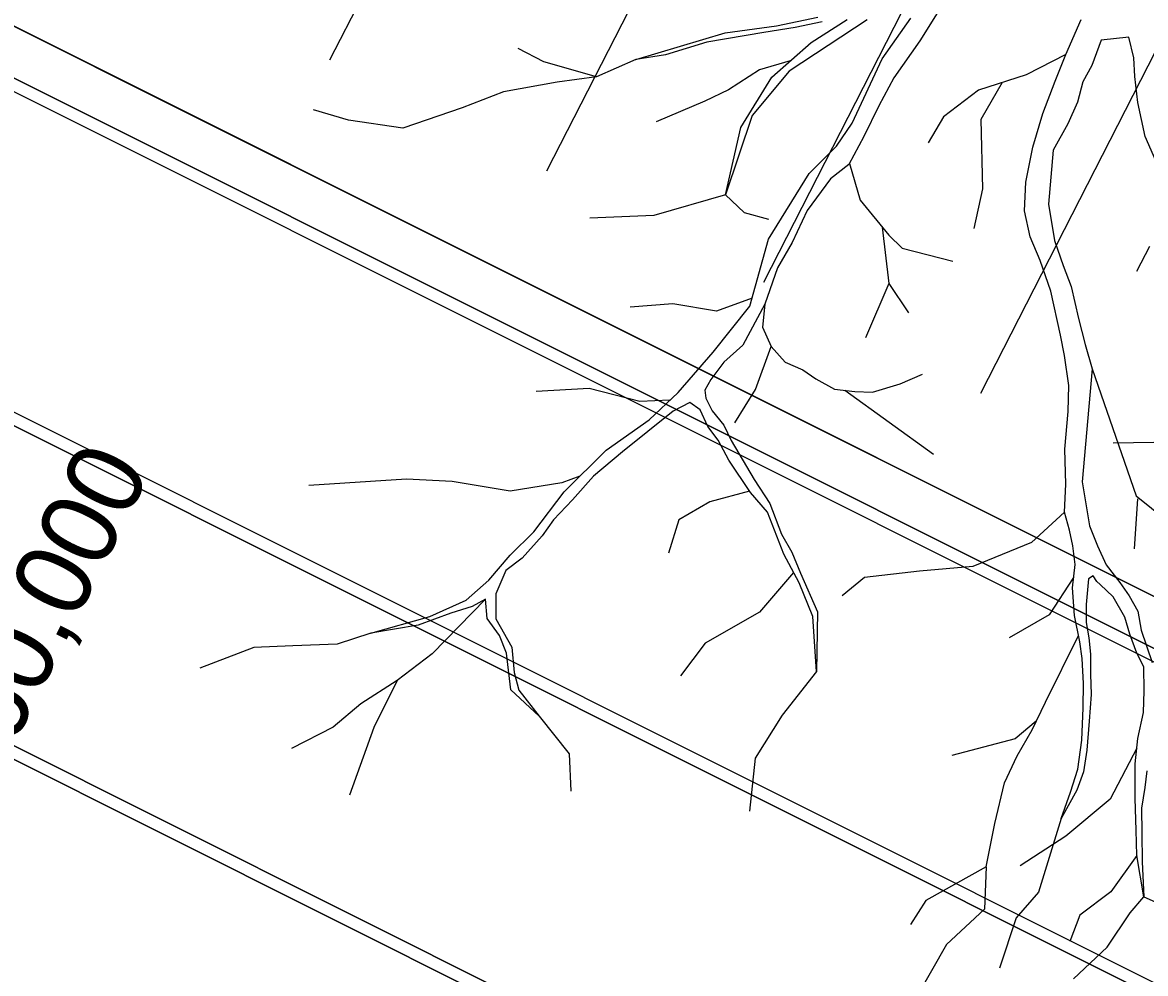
# Model space of a CAD drawing. Extents: x -504998 to -504814, y -1117353 to -1117234.
# Drawn here: x -504939.208 to -504934.599, y -1117264.364 to -1117260.463 of the extents above; entities that cross this region are included whole.
import ezdxf

# ---------------------------------------------------------------- set-up
doc = ezdxf.new("R2010")
doc.units = 0
for name, color, linetype in [('01_ST tenká', 7, 'Continuous'), ('03_POPIS', 7, 'Continuous'), ('10_STROMY', 7, 'Continuous'), ('_01_pl', 7, 'Continuous'), ('_01_sport_plochy', 7, 'Continuous'), ('_01_ST tenká', 7, 'Continuous'), ('_01_svah', 7, 'Continuous'), ('Default', 7, 'Continuous')]:
    doc.layers.add(name, color=color, linetype=linetype)

# ---------------------------------------------------------------- blocks, each defined once
blk = doc.blocks.new('stromm')
at = {"layer": 'Default'}
for p, q in [((-0.00824, -0.06434), (-0.02324, -0.07284)), ((-0.21026, -0.07639), (-0.22054, -0.07159)), ((-0.17472, -0.07388), (-0.1897, -0.08118)), ((-0.1149, -0.07164), (-0.12664, -0.0757)), ((-0.02324, -0.07284), (-0.04142, -0.0797)), ((-0.1897, -0.08118), (-0.21026, -0.07639)), ((-0.12664, -0.0757), (-0.13829, -0.08392)), ((-0.03233, -0.07627), (-0.03997, -0.09098)), ((-0.1897, -0.08118), (-0.20478, -0.08392)), ((-0.04142, -0.0797), (-0.05445, -0.09066)), ((-0.20478, -0.08392), (-0.22534, -0.08872)), ((-0.13829, -0.08392), (-0.1472, -0.08872)), ((-0.22534, -0.08872), (-0.24111, -0.09557)), ((-0.1472, -0.08872), (-0.16571, -0.09763)), ((-0.05445, -0.09066), (-0.05993, -0.10094)), ((-0.03997, -0.09098), (-0.03808, -0.11784)), ((-0.24111, -0.09557), (-0.26372, -0.10448)), ((-0.28497, -0.10242), (-0.29868, -0.099)), ((-0.26372, -0.10448), (-0.28497, -0.10242)), ((-0.09014, -0.11038), (-0.08529, -0.12438)), ((-0.03808, -0.11784), (-0.04073, -0.13334)), ((-0.13757, -0.12471), (-0.16502, -0.13395)), ((-0.13757, -0.12471), (-0.13006, -0.13121)), ((-0.08529, -0.12438), (-0.07364, -0.1374)), ((-0.16502, -0.13395), (-0.1897, -0.13601)), ((-0.13006, -0.13121), (-0.12047, -0.13326)), ((-0.07631, -0.13441), (-0.07272, -0.15613)), ((-0.07364, -0.1374), (-0.06815, -0.1422)), ((0.02756, -0.13717), (0.02303, -0.14714)), ((-0.06815, -0.1422), (-0.04838, -0.1464)), ((-0.07272, -0.15613), (-0.08084, -0.17762)), ((-0.07272, -0.15613), (-0.06461, -0.16708)), ((-0.12546, -0.16419), (-0.13899, -0.16982)), ((-0.15613, -0.16777), (-0.17257, -0.16982)), ((-0.13899, -0.16982), (-0.15613, -0.16777)), ((-0.12045, -0.16626), (-0.12098, -0.17524)), ((-0.12098, -0.17524), (-0.11728, -0.18264)), ((-0.12257, -0.19955), (-0.11728, -0.18264)), ((-0.11728, -0.18264), (-0.11147, -0.18845)), ((0.0075, -0.18561), (0.02679, -0.23402)), ((-0.11147, -0.18845), (-0.10459, -0.1911)), ((-0.10459, -0.1911), (-0.09931, -0.19427)), ((-0.06654, -0.1948), (-0.05808, -0.19057)), ((-0.09931, -0.19427), (-0.09191, -0.19797)), ((-0.07711, -0.19849), (-0.06654, -0.1948)), ((-0.12997, -0.21276), (-0.12257, -0.19955)), ((-0.09191, -0.19797), (-0.08398, -0.19849)), ((-0.08794, -0.19823), (-0.05241, -0.22145)), ((-0.08398, -0.19849), (-0.07711, -0.19849)), ((-0.18697, -0.20203), (-0.20753, -0.20409)), ((-0.16709, -0.20614), (-0.18697, -0.20203)), ((-0.15552, -0.20514), (-0.16709, -0.20614)), ((0.01698, -0.21385), (0.03274, -0.21288)), ((0.02679, -0.23402), (0.03913, -0.24293)), ((0.02733, -0.23514), (0.02698, -0.25449)), ((-0.19588, -0.23904), (-0.21576, -0.24315)), ((-0.18908, -0.2362), (-0.19588, -0.23904)), ((-0.12308, -0.23896), (-0.13831, -0.24383)), ((-0.2562, -0.24041), (-0.2939, -0.24452)), ((-0.23838, -0.24041), (-0.2562, -0.24041)), ((-0.21576, -0.24315), (-0.23838, -0.24041)), ((-0.13831, -0.24383), (-0.14996, -0.25137)), ((-0.00068, -0.24161), (-0.01296, -0.25389)), ((-0.14996, -0.25137), (-0.15339, -0.26439)), ((-0.01296, -0.25389), (-0.03525, -0.26417)), ((-0.03525, -0.26417), (-0.05582, -0.26692)), ((-0.10458, -0.26969), (-0.11706, -0.28564)), ((-0.05582, -0.26692), (-0.07706, -0.27034)), ((0.004, -0.2667), (-0.0048, -0.2816)), ((-0.07706, -0.27034), (-0.08529, -0.27788)), ((-0.0048, -0.2816), (-0.01988, -0.29119)), ((-0.22348, -0.28543), (-0.24318, -0.30756)), ((-0.11706, -0.28564), (-0.13762, -0.29865)), ((-0.00472, -0.31547), (0.0069, -0.2891)), ((-0.13762, -0.29865), (-0.14653, -0.31167)), ((-0.26725, -0.30058), (-0.28019, -0.30551)), ((-0.31241, -0.30825), (-0.33297, -0.31716)), ((-0.29733, -0.30688), (-0.31241, -0.30825)), ((-0.28019, -0.30551), (-0.29733, -0.30688)), ((-0.24318, -0.30756), (-0.2562, -0.31852)), ((-0.09402, -0.30757), (-0.10654, -0.32516)), ((-0.00942, -0.32642), (-0.00472, -0.31547)), ((-0.2562, -0.31852), (-0.26991, -0.32812)), ((-0.2562, -0.31852), (-0.26442, -0.33703)), ((-0.10654, -0.32516), (-0.11613, -0.3423)), ((-0.00793, -0.32294), (-0.01577, -0.33025)), ((-0.01474, -0.33675), (-0.00942, -0.32642)), ((-0.26991, -0.32812), (-0.28019, -0.33771)), ((-0.20059, -0.32986), (-0.18834, -0.34388)), ((-0.01577, -0.33025), (-0.04011, -0.33779)), ((0.03149, -0.33171), (0.02199, -0.35189)), ((-0.28019, -0.33771), (-0.29596, -0.34662)), ((-0.26442, -0.33703), (-0.27265, -0.36376)), ((-0.01913, -0.34738), (-0.01474, -0.33675)), ((-0.18834, -0.34388), (-0.18697, -0.35827)), ((-0.11613, -0.3423), (-0.1175, -0.36285)), ((-0.02226, -0.36334), (-0.01913, -0.34738)), ((0.02199, -0.35189), (0.00554, -0.36696)), ((0.00343, -0.36018), (-0.00412, -0.38918)), ((-0.02476, -0.38024), (-0.02226, -0.36334)), ((0.00554, -0.36696), (-0.01159, -0.3793)), ((0.03338, -0.37322), (0.02399, -0.38781)), ((-0.02476, -0.38024), (-0.04759, -0.39437)), ((-0.02476, -0.38024), (-0.02468, -0.39672)), ((-0.00412, -0.38918), (-0.01234, -0.39946)), ((0.02399, -0.38781), (0.01233, -0.39741)), ((0.03174, -0.39551), (0.03679, -0.38911)), ((0.03679, -0.38911), (0.04716, -0.39322)), ((-0.04759, -0.39437), (-0.05307, -0.40397)), ((0.02355, -0.40928), (0.03174, -0.39551)), ((-0.02468, -0.39672), (-0.03874, -0.41111)), ((-0.01234, -0.39946), (-0.01782, -0.41934)), ((0.01233, -0.39741), (0.00891, -0.40769)), ((0.02355, -0.40928), (0.01096, -0.42208)), ((-0.03874, -0.41111), (-0.04902, -0.43099))]:
    blk.add_line(p, q, dxfattribs=at)
for points in [[(-0.05311, -0.04048), (-0.06495, -0.06163), (-0.07447, -0.07643), (-0.07975, -0.08753), (-0.08504, -0.09968), (-0.09032, -0.11078), (-0.09719, -0.11659), (-0.10565, -0.12927), (-0.11094, -0.14195), (-0.11622, -0.15199), (-0.12045, -0.16626), (-0.12825, -0.18252), (-0.13525, -0.18951), (-0.14001, -0.19638), (-0.14212, -0.20061), (-0.14159, -0.20378), (-0.13895, -0.20853), (-0.13419, -0.21382), (-0.13102, -0.21963), (-0.12151, -0.23443), (-0.11495, -0.24344), (-0.10988, -0.25504), (-0.10565, -0.26191), (-0.10195, -0.26983), (-0.09461, -0.28451), (-0.09402, -0.30757), (-0.09641, -0.28636), (-0.10223, -0.27365), (-0.10866, -0.26277), (-0.11575, -0.24681), (-0.1227, -0.23947), (-0.13164, -0.22739), (-0.13615, -0.21976), (-0.14033, -0.21468), (-0.14362, -0.2084), (-0.1478, -0.20572), (-0.15407, -0.2093), (-0.17294, -0.22598), (-0.18375, -0.23596), (-0.1915, -0.24538), (-0.19857, -0.25346), (-0.20261, -0.25986), (-0.21001, -0.26895), (-0.21608, -0.27399), (-0.21952, -0.2832), (-0.21909, -0.29287), (-0.21237, -0.30361), (-0.21103, -0.31337), (-0.20901, -0.3201), (-0.20059, -0.32986), (-0.21203, -0.3201), (-0.21439, -0.30596), (-0.21742, -0.29924), (-0.22247, -0.29284), (-0.22348, -0.28543), (-0.22853, -0.28846), (-0.23661, -0.29149), (-0.24906, -0.29668), (-0.26725, -0.30058), (-0.24469, -0.29318), (-0.23088, -0.28611), (-0.22247, -0.27803), (-0.21473, -0.26793), (-0.20597, -0.25851), (-0.19486, -0.24246), (-0.17935, -0.22566), (-0.16322, -0.21307), (-0.15245, -0.20197), (-0.13957, -0.18574), (-0.12618, -0.16732), (-0.12019, -0.14112), (-0.10559, -0.11494), (-0.09548, -0.10384), (-0.08972, -0.0947), (-0.07929, -0.06918), (-0.06889, -0.05302)], [(-0.08573, -0.05433), (-0.11504, -0.07565), (-0.12862, -0.09341), (-0.13757, -0.12471), (-0.13288, -0.09828), (-0.12174, -0.07826), (-0.10713, -0.06412), (-0.09358, -0.05464)], [(-0.10319, -0.05592), (-0.11355, -0.05868), (-0.12565, -0.0611), (-0.14751, -0.06582), (-0.16332, -0.07146), (-0.17472, -0.07388), (-0.1406, -0.06197), (-0.12081, -0.05834), (-0.10491, -0.05419)], [(0.02849, -0.10392), (0.02402, -0.09464), (0.02058, -0.08159), (0.01884, -0.07158), (0.01815, -0.06437), (0.01595, -0.05645), (0.00519, -0.05816), (0.00201, -0.06815), (-0.00109, -0.07467), (-0.0028, -0.08257), (-0.00624, -0.09116), (-0.01148, -0.10164), (-0.01232, -0.12256), (-0.00933, -0.1365), (-0.00555, -0.14611), (-0.00212, -0.15401), (0.00132, -0.16637), (0.00441, -0.17634), (0.0075, -0.18561), (0.00564, -0.2295), (0.00922, -0.2464), (0.01265, -0.25396), (0.01643, -0.26117), (0.02193, -0.26785), (0.02586, -0.27277), (0.02947, -0.27867), (0.03111, -0.28588), (0.0359, -0.2982)], [(0.0357, -0.3403), (0.03531, -0.34683), (0.03433, -0.35482), (0.03494, -0.36452), (0.03556, -0.37557), (0.03679, -0.38911), (0.03338, -0.37322), (0.03273, -0.36338), (0.03174, -0.35125), (0.03109, -0.33781), (0.03174, -0.32798), (0.03338, -0.31781), (0.03338, -0.30929), (0.03273, -0.30011), (0.02978, -0.29487), (0.02683, -0.28765), (0.02453, -0.2811), (0.01961, -0.27356), (0.01436, -0.26897), (0.01311, -0.2679), (0.01155, -0.26571), (0.00981, -0.26695), (0.00936, -0.27697), (0.00967, -0.28386), (0.01092, -0.28981), (0.01186, -0.29607), (0.01218, -0.30389), (0.0128, -0.31171), (0.01249, -0.32204), (0.01218, -0.3333), (0.01124, -0.34175), (0.00904, -0.34895), (0.00343, -0.36018), (0.00654, -0.34989), (0.00904, -0.34081), (0.00998, -0.32955), (0.00998, -0.31703), (0.00967, -0.30764), (0.00873, -0.29794), (0.00752, -0.29157), (0.00498, -0.28136), (0.00372, -0.27072), (0.00435, -0.26164), (0.0031, -0.25444), (0.00153, -0.2485), (-0.00068, -0.24161), (-0.00066, -0.23066), (-0.0016, -0.21721), (-0.00097, -0.2025), (-0.00128, -0.19248), (-0.00347, -0.18091), (-0.00535, -0.17308), (-0.0098, -0.15622), (-0.01456, -0.1446), (-0.01879, -0.13561), (-0.02143, -0.12557), (-0.02143, -0.11448), (-0.01931, -0.10074), (-0.01614, -0.08753), (-0.01191, -0.07484), (-0.00822, -0.06427), (-0.00293, -0.05053)], [(-0.05311, -0.04048), (-0.06495, -0.06163), (-0.07447, -0.07643), (-0.07975, -0.08753), (-0.08504, -0.09968), (-0.09032, -0.11078), (-0.09719, -0.11659), (-0.10565, -0.12927), (-0.11094, -0.14195), (-0.11622, -0.15199), (-0.12045, -0.16626), (-0.12825, -0.18252), (-0.13525, -0.18951), (-0.14001, -0.19638), (-0.14212, -0.20061), (-0.14159, -0.20378), (-0.13895, -0.20853), (-0.13419, -0.21382), (-0.13102, -0.21963), (-0.12151, -0.23443), (-0.11495, -0.24344), (-0.10988, -0.25504), (-0.10565, -0.26191), (-0.10195, -0.26983), (-0.09461, -0.28451), (-0.09402, -0.30757), (-0.09641, -0.28636), (-0.10223, -0.27365), (-0.10866, -0.26277), (-0.11575, -0.24681), (-0.1227, -0.23947), (-0.13164, -0.22739), (-0.13615, -0.21976), (-0.14033, -0.21468), (-0.14362, -0.2084), (-0.1478, -0.20572), (-0.15407, -0.2093), (-0.17294, -0.22598), (-0.18375, -0.23596), (-0.1915, -0.24538), (-0.19857, -0.25346), (-0.20261, -0.25986), (-0.21001, -0.26895), (-0.21608, -0.27399), (-0.21952, -0.2832), (-0.21909, -0.29287), (-0.21237, -0.30361), (-0.21103, -0.31337), (-0.20901, -0.3201), (-0.20059, -0.32986), (-0.21203, -0.3201), (-0.21439, -0.30596), (-0.21742, -0.29924), (-0.22247, -0.29284), (-0.22348, -0.28543), (-0.22853, -0.28846), (-0.23661, -0.29149), (-0.24906, -0.29668), (-0.26725, -0.30058), (-0.24469, -0.29318), (-0.23088, -0.28611), (-0.22247, -0.27803), (-0.21473, -0.26793), (-0.20597, -0.25851), (-0.19486, -0.24246), (-0.17935, -0.22566), (-0.16322, -0.21307), (-0.15245, -0.20197), (-0.13957, -0.18574), (-0.12618, -0.16732), (-0.12019, -0.14112), (-0.10559, -0.11494), (-0.09548, -0.10384), (-0.08972, -0.0947), (-0.07929, -0.06918), (-0.06889, -0.05302)], [(-0.08573, -0.05433), (-0.11504, -0.07565), (-0.12862, -0.09341), (-0.13757, -0.12471), (-0.13288, -0.09828), (-0.12174, -0.07826), (-0.10713, -0.06412), (-0.09358, -0.05464)], [(-0.10319, -0.05592), (-0.11355, -0.05868), (-0.12565, -0.0611), (-0.14751, -0.06582), (-0.16332, -0.07146), (-0.17472, -0.07388), (-0.1406, -0.06197), (-0.12081, -0.05834), (-0.10491, -0.05419)], [(0.02849, -0.10392), (0.02402, -0.09464), (0.02058, -0.08159), (0.01884, -0.07158), (0.01815, -0.06437), (0.01595, -0.05645), (0.00519, -0.05816), (0.00201, -0.06815), (-0.00109, -0.07467), (-0.0028, -0.08257), (-0.00624, -0.09116), (-0.01148, -0.10164), (-0.01232, -0.12256), (-0.00933, -0.1365), (-0.00555, -0.14611), (-0.00212, -0.15401), (0.00132, -0.16637), (0.00441, -0.17634), (0.0075, -0.18561), (0.00564, -0.2295), (0.00922, -0.2464), (0.01265, -0.25396), (0.01643, -0.26117), (0.02193, -0.26785), (0.02586, -0.27277), (0.02947, -0.27867), (0.03111, -0.28588), (0.0359, -0.2982)], [(0.0357, -0.3403), (0.03531, -0.34683), (0.03433, -0.35482), (0.03494, -0.36452), (0.03556, -0.37557), (0.03679, -0.38911), (0.03338, -0.37322), (0.03273, -0.36338), (0.03174, -0.35125), (0.03109, -0.33781), (0.03174, -0.32798), (0.03338, -0.31781), (0.03338, -0.30929), (0.03273, -0.30011), (0.02978, -0.29487), (0.02683, -0.28765), (0.02453, -0.2811), (0.01961, -0.27356), (0.01436, -0.26897), (0.01311, -0.2679), (0.01155, -0.26571), (0.00981, -0.26695), (0.00936, -0.27697), (0.00967, -0.28386), (0.01092, -0.28981), (0.01186, -0.29607), (0.01218, -0.30389), (0.0128, -0.31171), (0.01249, -0.32204), (0.01218, -0.3333), (0.01124, -0.34175), (0.00904, -0.34895), (0.00343, -0.36018), (0.00654, -0.34989), (0.00904, -0.34081), (0.00998, -0.32955), (0.00998, -0.31703), (0.00967, -0.30764), (0.00873, -0.29794), (0.00752, -0.29157), (0.00498, -0.28136), (0.00372, -0.27072), (0.00435, -0.26164), (0.0031, -0.25444), (0.00153, -0.2485), (-0.00068, -0.24161), (-0.00066, -0.23066), (-0.0016, -0.21721), (-0.00097, -0.2025), (-0.00128, -0.19248), (-0.00347, -0.18091), (-0.00535, -0.17308), (-0.0098, -0.15622), (-0.01456, -0.1446), (-0.01879, -0.13561), (-0.02143, -0.12557), (-0.02143, -0.11448), (-0.01931, -0.10074), (-0.01614, -0.08753), (-0.01191, -0.07484), (-0.00822, -0.06427), (-0.00293, -0.05053)]]:
    blk.add_lwpolyline(points, dxfattribs=at)

msp = doc.modelspace()

# ---------------------------------------------------------------- linework, layer by layer
at = {"layer": '01_ST tenká'}
msp.add_line((-504900.7972, -1117279.6967), (-504948.1838, -1117256.0088), dxfattribs=at)
at = {"layer": '_01_pl'}
msp.add_lwpolyline([(-504937.1881, -1117248.33), (-504911.1347, -1117267.929), (-504901.2482, -1117274.9388), (-504900.5935, -1117275.3475), (-504902.3736, -1117278.9087), (-504942.9722, -1117258.614), (-504941.0946, -1117254.858), (-504941.0341, -1117254.737)], close=True, dxfattribs=at)
for points in [[(-504948.1838, -1117256.0088), (-504883.1034, -1117288.5416), (-504884.4448, -1117291.225), (-504886.0794, -1117290.4079), (-504886.0783, -1117290.4057), (-504900.5273, -1117283.1828), (-504900.8848, -1117283.898), (-504903.7177, -1117282.4818), (-504910.4257, -1117279.1273), (-504909.9784, -1117278.2329), (-504912.6616, -1117276.8911), (-504913.1089, -1117277.7855), (-504939.8496, -1117264.4132)], [(-504949.3862, -1117258.4143), (-504884.5343, -1117290.8451), (-504883.4161, -1117288.6091), (-504948.2684, -1117256.1781)]]:
    msp.add_lwpolyline(points, dxfattribs=at)
at = {"layer": '_01_sport_plochy'}
for points in [[(-504884.8258, -1117287.9042), (-504885.9439, -1117290.1402), (-504948.552, -1117258.8314), (-504947.4338, -1117256.5954)], [(-504885.9663, -1117290.0731), (-504948.4849, -1117258.8091), (-504947.9593, -1117257.7582), (-504885.4408, -1117289.0222)], [(-504885.4408, -1117289.0222), (-504947.9593, -1117257.7582), (-504948.4849, -1117258.8091), (-504885.9663, -1117290.0731)]]:
    msp.add_lwpolyline(points, close=True, dxfattribs=at)
at = {"layer": '_01_ST tenká'}
for p, q in [((-504947.937, -1117257.7134), (-504885.4184, -1117288.9775)), ((-504947.9593, -1117257.7582), (-504885.4408, -1117289.0222))]:
    msp.add_line(p, q, dxfattribs=at)
msp.add_lwpolyline([(-504951.6824, -1117257.266), (-504885.9439, -1117290.1402), (-504884.8258, -1117287.9042), (-504950.5642, -1117255.03)], close=True, dxfattribs=at)
for points in [[(-504885.4184, -1117288.9775), (-504884.8929, -1117287.9265), (-504947.4114, -1117256.6625)], [(-504948.4849, -1117258.8091), (-504885.9663, -1117290.0731), (-504885.4408, -1117289.0222)]]:
    msp.add_lwpolyline(points, dxfattribs=at)
at = {"layer": '_01_svah'}
for p, q in [((-504935.9067, -1117256.6285), (-504937.9478, -1117260.618)), ((-504935.0474, -1117257.1444), (-504937.0575, -1117261.0734)), ((-504934.1881, -1117257.6604), (-504936.1672, -1117261.5289)), ((-504933.3287, -1117258.1763), (-504935.277, -1117261.9844))]:
    msp.add_line(p, q, dxfattribs=at)

# ---------------------------------------------------------------- block references
at = {"layer": '10_STROMY', "xscale": 10.58270031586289, "yscale": 10.582699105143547, "rotation": -2.5987541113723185}
msp.add_blockref('stromm', (-504934.8086, -1117259.9181), dxfattribs=at)

# ---------------------------------------------------------------- texts
at = {"layer": '03_POPIS'}
msp.add_text('60,000', height=0.31278, rotation=63.3672, dxfattribs=at).set_placement((-504939.2524, -1117263.4449))

doc.saveas('drawing.dxf')
